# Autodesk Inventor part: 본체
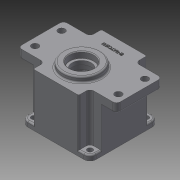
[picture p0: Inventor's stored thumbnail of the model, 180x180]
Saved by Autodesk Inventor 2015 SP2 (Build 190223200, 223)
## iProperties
Created: 2015-06
Part Number: 본체
Material: 일반
Document SubType Name: Modeling
Designer: AMC
Density: 1 g/cm^3
Appearance: 기본값
Author: AMC
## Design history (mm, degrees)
sketch "스케치1"
  geometry: L1 (-45, 45)-(45, 45); L2 (45, 45)-(45, -45); L3 (45, -45)-(-45, -45); L4 (-45, -45)-(-45, 45); 3 further points
  constraints: 8 end point, 2 midpoint, 2 parallel, 1 horizontal, 1 horizontal alignment, 1 perpendicular, 1 vertical alignment
  dimensions: "d0" = 90 distance of L2.end L3.end; "d1" = 90 distance of L1.end L2.end
extrude "돌출1" new body sketch "스케치1" distance "d2" = 70; taper "d3" = 0 deg
sketch "스케치2"
  geometry: L1 (-65, 30)-(65, 30); L2 (65, 30)-(65, -30); L3 (65, -30)-(-65, -30); L4 (-65, -30)-(-65, 30); 3 further points
  constraints: 8 end point, 2 midpoint, 2 parallel, 1 horizontal, 1 horizontal alignment, 1 perpendicular, 1 vertical alignment
  dimensions: "d4" = 60 distance between parallel lines of L3 L1; "d5" = 130 distance between parallel lines of L2 L4
extrude "돌출2" join sketch "스케치2" distance "d6" = 12; taper "d7" = 0 deg
sketch "스케치3"
  geometry: C1 r 25 at (0, -11); 1 further point
  constraints: 1 centre point, 1 vertical alignment
  dimensions: "d8" = 50 diameter of C1; "d9" = 11 distance of point (0, 0) C1.centre
extrude "돌출3" join sketch "스케치3" distance "d10" = 7; taper "d11" = 0 deg
sketch "스케치4"
  geometry: C1 r 40 at (0, 0); 1 further point
  constraints: 1 centre point, 1 coincident
  dimensions: "d12" = 80 diameter of C1
extrude "돌출4" cut sketch "스케치4" distance "d13" = 9; taper "d14" = 0 deg
sketch "스케치5"
  geometry: C1 r 39 at (0, 0); 1 further point
  constraints: 1 centre point, 1 coincident
  dimensions: "d15" = 78 diameter of C1
extrude "돌출5" cut sketch "스케치5" distance "d16" = 52; taper "d17" = 0 deg
sketch "스케치6"
  geometry: L1 (0, 0)-(0, -10.322); L2 (0, 0)-(24.749, -24.749); C1 r 39 at (0, 0) reference; C2 r 4 at (24.749, -24.749)
  constraints: 4 end point, 1 centre point, 1 coincident, 1 vertical
  dimensions: "d18" = 45 deg angle of L1 L2; "d19" = 35 distance of L1.start L2.end; "d23" = 8 diameter of C2
extrude "돌출6" join sketch "스케치6" distance "d24" = 52; taper "d25" = 0 deg
sketch "스케치7"
  geometry: L1 (-0.145, -5.511)-(-2.828, -2.828); L2 (-24.749, 24.749)-(-24.749, 16.128); L3 (-24.749, 24.749)-(-14.182, 24.749); L4 (5.511, 0.145)-(2.828, 2.828); A1 r 39 centre (-24.749, 24.749) between (2.828, -2.828) and (5.511, 0.145) reference; A2 r 4 centre (0, 0) between (2.828, -2.828) and (2.828, 2.828) reference; 1 further point
  constraints: 8 end point, 4 point on circle, 2 tangent, 1 horizontal, 1 vertical
  dimensions: "d27" = 45 deg angle of L2 L1; "d28" = 45 deg angle of L3 L4
extrude "돌출7" join sketch "스케치7" distance "d29" = 52; taper "d30" = 0 deg
sketch "스케치8"
  geometry: C1 r 20.5 at (0, -11); C2 r 14 at (0, 20); 1 further point
  constraints: 2 centre point, 2 vertical alignment
  dimensions: "d34" = 41 diameter of C1; "d35" = 28 diameter of C2; "d36" = 11 distance of point (0, 0) C1.centre; "d37" = 20 distance of C2.centre point (0, 0)
extrude "돌출8" join sketch "스케치8" distance "d38" = 7; taper "d39" = 0 deg
hole "구멍1" diameter "d42" = 25; stored, may be unused: countersink angle "d46" = 90 deg, drill point angle "d48" = 118 deg; dims "d43" = 6, "d44" = 32, "d45" = 8, "d47" = 8, "d58" = 10, "d59" = 10
hole "구멍2" diameter "d51" = 25; stored, may be unused: countersink angle "d55" = 90 deg, drill point angle "d57" = 118 deg; dims "d52" = 6, "d53" = 35, "d54" = 10, "d56" = 8, "d60" = 10, "d61" = 10
hole "구멍3" diameter "d64" = 19; stored, may be unused: countersink angle "d68" = 90 deg, drill point angle "d70" = 0 deg; dims "d65" = 6, "d66" = 22, "d67" = 7, "d69" = 8, "d71" = 10, "d72" = 10
fillet "모깎기1" dims "d73" = 5
sketch "스케치10"
  geometry: C1 r 4.5 at (55, 17.5); C2 r 4.5 at (55, -17.5); 2 further points
  constraints: 2 centre point, 1 coincident
  dimensions: "d74" = 55 horizontal distance of point (0, 0) point (55, 17.5); "d75" = 17.5 vertical distance of point (0, 0) point (55, 17.5); "d76" = 9 diameter of C1; "d77" = 9 diameter of C2; "d78" = 55 horizontal distance of point (0, 0) C2.centre; "d79" = 17.5 vertical distance of point (0, 0) C2.centre
extrude "돌출9" cut sketch "스케치10" stored distance "d80" = 7; taper "d81" = 0 deg
fillet "모깎기2" dims "d82" = 8
sketch "스케치11"
  geometry: L1 (37, -45)-(-37, -45) reference; L2 (45, -30)-(30, -30); L3 (30, -30)-(30, -45); L4 (30, -45)-(45, -45); L5 (45, -45)-(45, -30); 1 further point
  constraints: 8 end point, 2 parallel, 1 horizontal, 1 perpendicular, 1 point on line
  dimensions: "d83" = 30 distance from line of point (0, 0) L3
extrude "돌출10" cut sketch "스케치11" distance "d84" = 63; taper "d85" = 0 deg
fillet "모깎기3" dims "d86" = 5
sketch "스케치13"
  geometry: C1 r 3.5 at (37, -37); C2 r 3.5 at (37, 37); C3 r 3.5 at (-37, -37); C4 r 3.5 at (-37, 37); A1 r 8 centre (37, -37) between (37, -45) and (45, -37) reference; A2 r 8 centre (-37, -37) between (-45, -37) and (-37, -45) reference; A3 r 8 centre (-37, 37) between (-37, 45) and (-45, 37) reference; A4 r 8 centre (37, 37) between (45, 37) and (37, 45) reference; 1 further point
  constraints: 4 centre point, 4 coincident
  dimensions: "d87" = 7 diameter of C1; "d88" = 7 diameter of C2; "d89" = 7 diameter of C3; "d90" = 7 diameter of C4
extrude "돌출11" cut sketch "스케치13" distance "d91" = 63; taper "d92" = 0 deg
sketch "스케치14"
  geometry: A1 r 4 centre (24.749, -24.749) between (27.577, -21.92) and (21.92, -27.577) reference; 3 further points
hole "구멍4" sketch "스케치14" at (24.749, -24.749) diameter "d94" = 3.459; stored, may be unused: countersink angle "d98" = 90 deg, drill point angle "d100" = 118 deg; dims "d95" = 12, "d96" = 22, "d97" = 7, "d99" = 15
fillet "모깎기5" dims "d104" = 0.3
fillet "모깎기6" dims "d105" = 2
fillet "모깎기7" dims "d106" = 3
fillet "모깎기8" dims "d107" = 3.5
fillet "모깎기9" dims "d108" = 2
fillet "모깎기10" dims "d109" = 2
fillet "모깎기11" dims "d110" = 2
fillet "모깎기13" dims "d112" = 2
fillet "모깎기14" dims "d113" = 2
fillet "모깎기15" dims "d114" = 2
chamfer "모따기1" distance "d115" = 1; stored, may be unused: second distance "d116" = 2, angle "d117" = 45 deg
sketch "스케치15"
  geometry: L1 (28, 45)-(-28, 45) reference; 2 further points
  constraints: 1 vertical alignment, 1 other
  dimensions: "d118" = 15 distance from line of L1 point (0, 30)
feature "엠보싱1" sketch "스케치15" dims "d10" = 7, "d11" = 0, "d119" = 0.5, "d120" = 0
fillet "모깎기16" dims "d121" = 2
node "솔리드1"
pattern_circular "원형 패턴1" dims angle "d32" = 360 deg
mirror "대칭1"
mirror "대칭2"
mirror "대칭3"
pattern_circular "원형 패턴2" dims angle "d102" = 360 deg
node "작업 평면1"
